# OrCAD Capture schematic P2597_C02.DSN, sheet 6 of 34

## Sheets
6 28_5V & 3V3 Vregs: size Custom
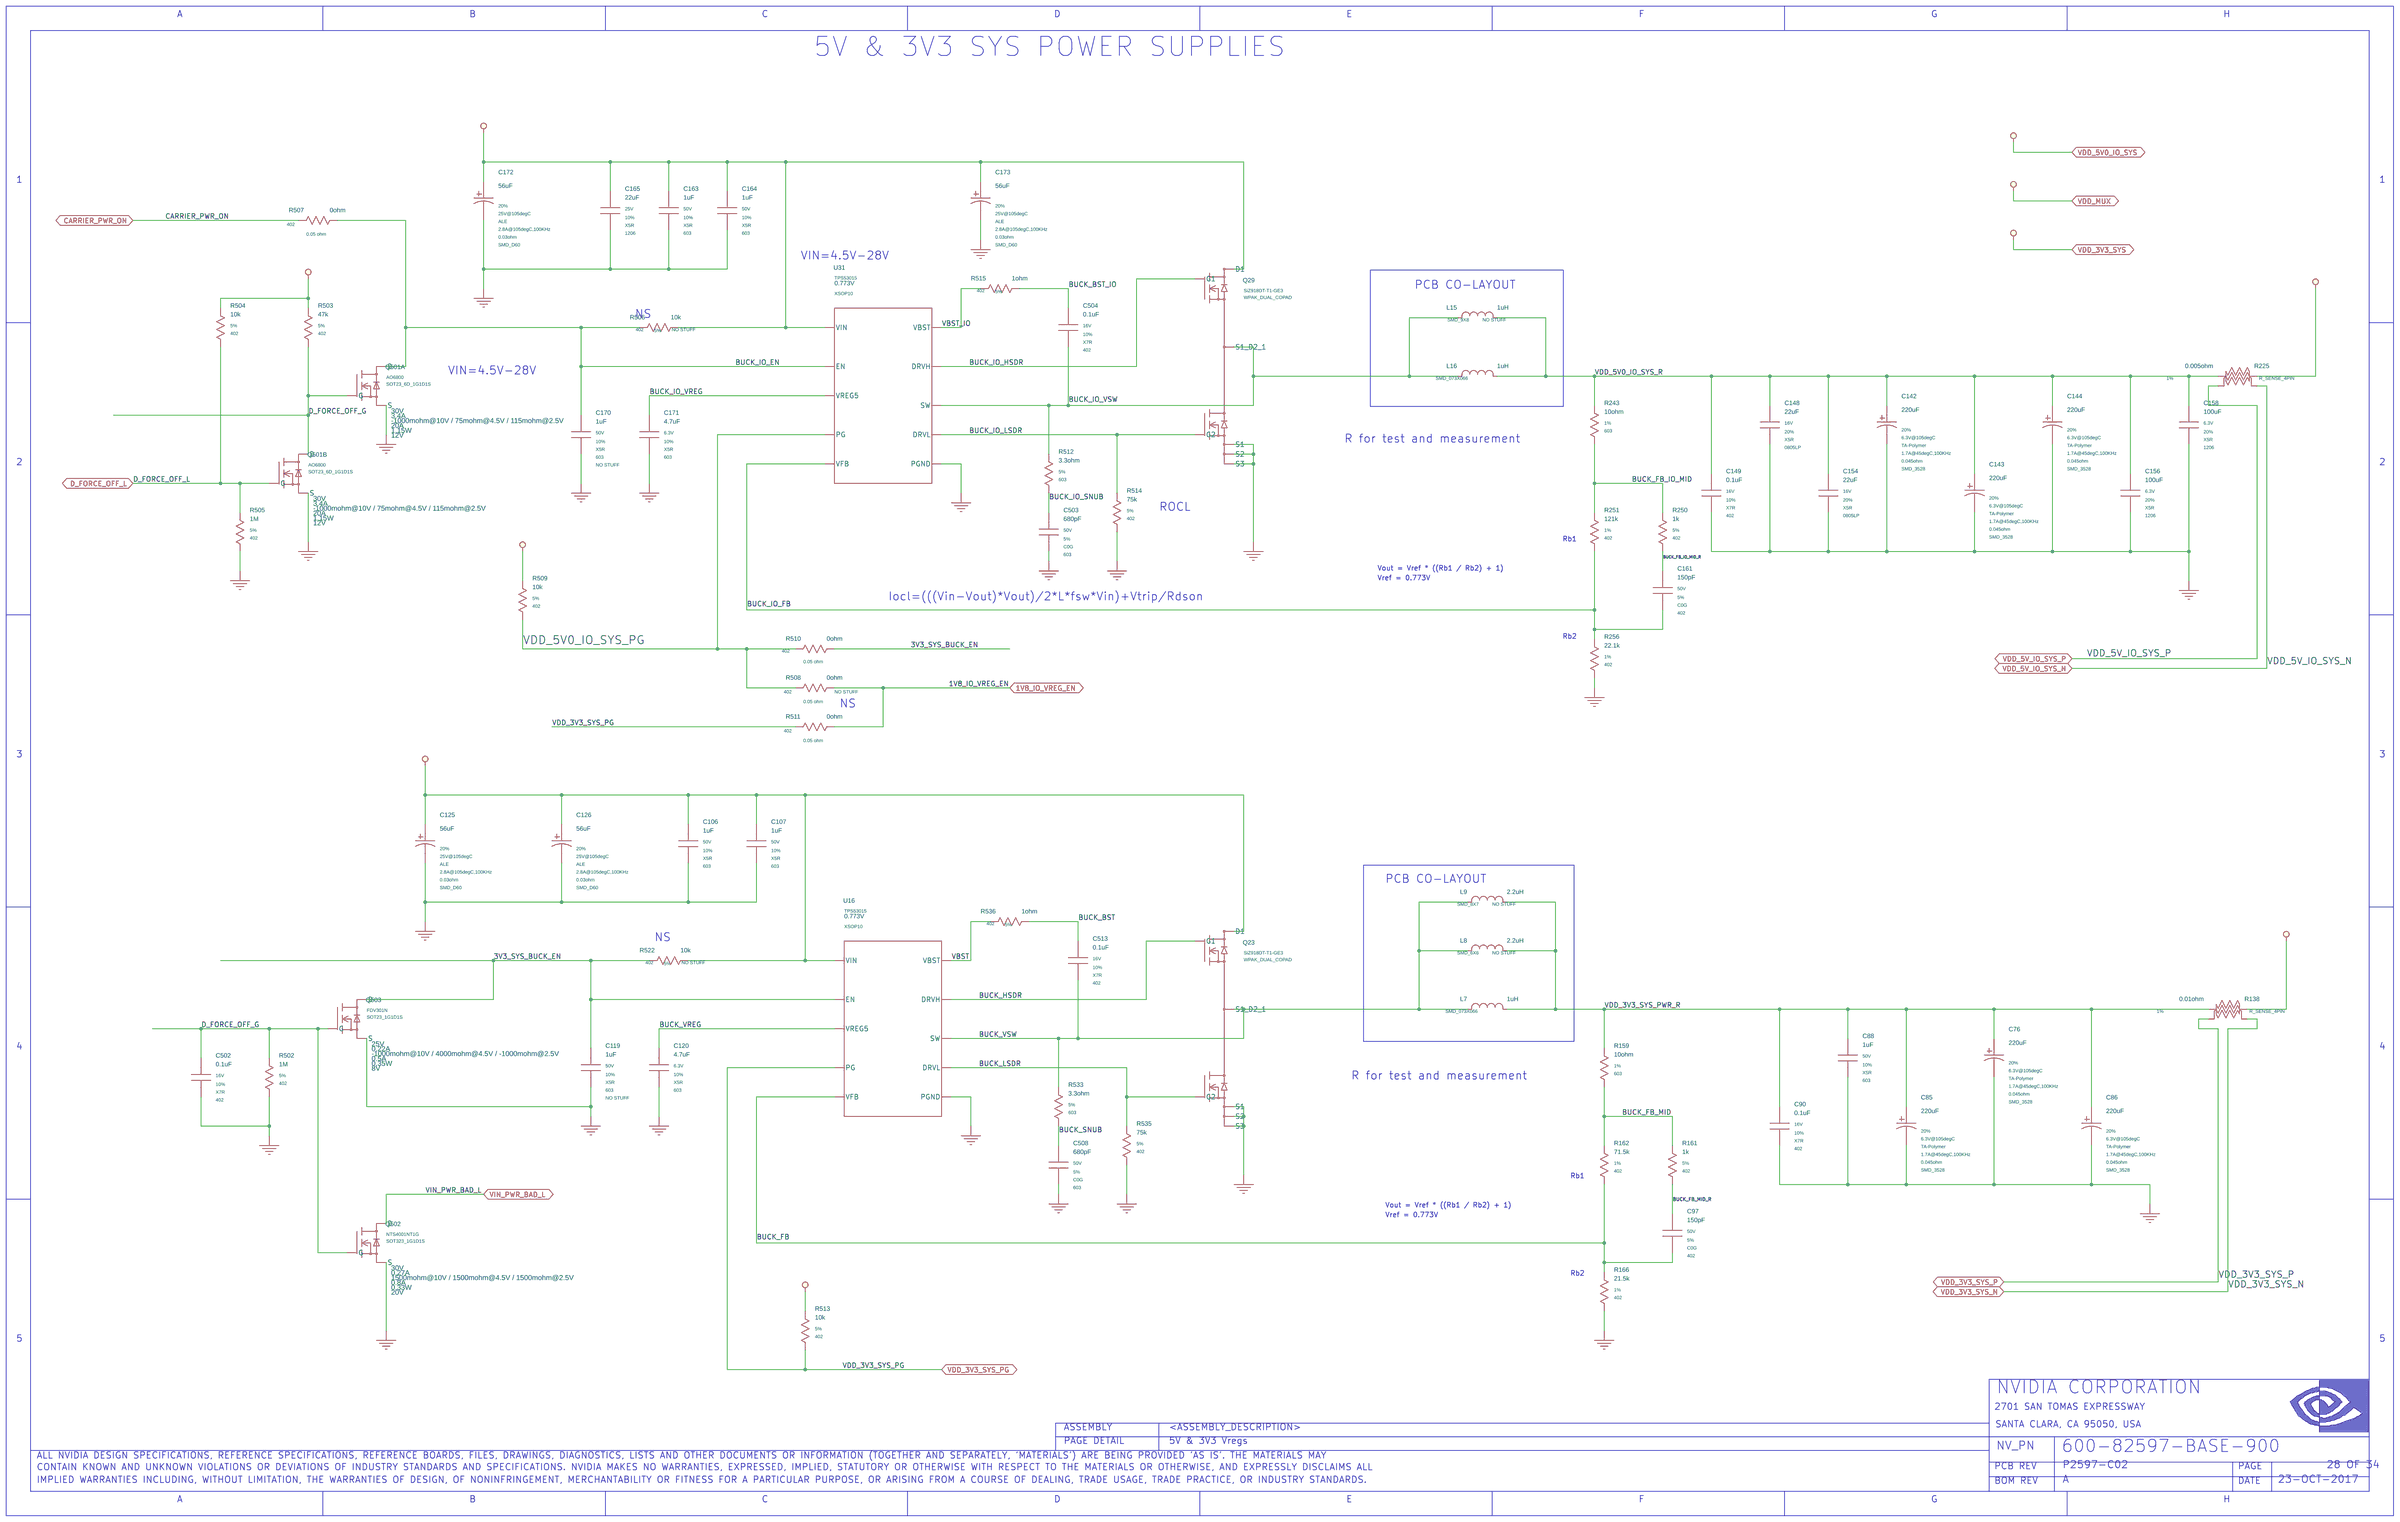
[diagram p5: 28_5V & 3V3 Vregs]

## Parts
C76  220uF  [CAP_SMD_3528]
C85  220uF  [CAP_SMD_3528]
C86  220uF  [CAP_SMD_3528]
C88  1uF  [603]
C90  0.1uF  [402]
C97  150pF  [402]
C106  1uF  [603]
C107  1uF  [603]
C119  1uF  [603]
C120  4.7uF  [603]
C125  56uF  [CAP_SMD_066X066]
C126  56uF  [CAP_SMD_066X066]
C142  220uF  [CAP_SMD_3528]
C143  220uF  [CAP_SMD_3528]
C144  220uF  [CAP_SMD_3528]
C148  22uF  [805]
C149  0.1uF  [402]
C154  22uF  [805]
C156  100uF  [1206]
C158  100uF  [1206]
C161  150pF  [402]
C163  1uF  [603]
C164  1uF  [603]
C165  22uF  [1206]
C170  1uF  [603]
C171  4.7uF  [603]
C172  56uF  [CAP_SMD_066X066]
C173  56uF  [CAP_SMD_066X066]
C502  0.1uF  [402]
C503  680pF  [603]
C504  0.1uF  [402]
C508  680pF  [603]
C513  0.1uF  [402]
L7  1uH  [IND_NONRKO_SMD_073X066]
L8  2.2uH  [IND_NONRKO_SMD_065X069]
L9  2.2uH  [IND_NONRKO_SMD_078X072]
L15  1uH  [IND_NONRKO_SMD_088X084]
L16  1uH  [IND_NONRKO_SMD_073X066]
Q23  Q_FET_N_ENH  [DFET_SMD_056X052_VIAS]
Q29  Q_FET_N_ENH  [DFET_SMD_056X052_VIAS]
Q501  Q_FET_N_ENH  [SOT23_6]  (sections A,B)
Q502  Q_FET_N_ENH  [SOT323]
Q503  Q_FET_N_ENH  [SOT23]
R138  0.01ohm  [RES_04_SMD_015X032]
R159  10ohm  [603]
R161  1k  [402]
R162  71.5k  [402]
R166  21.5k  [402]
R225  0.005ohm  [RES_04_SMD_015X032]
R243  10ohm  [603]
R250  1k  [402]
R251  121k  [402]
R256  22.1k  [402]
R502  1M  [402]
R503  47k  [402]
R504  10k  [402]
R505  1M  [402]
R506  10k  [402]
R507  0ohm  [402]
R508  0ohm  [402]
R509  10k  [402]
R510  0ohm  [402]
R511  0ohm  [402]
R512  3.3ohm  [603]
R513  10k  [402]
R514  75k  [402]
R515  1ohm  [402]
R522  10k  [402]
R533  3.3ohm  [603]
R535  75k  [402]
R536  1ohm  [402]
U16  0.773V  [XSOP10_P050_030X030]
U31  0.773V  [XSOP10_P050_030X030]

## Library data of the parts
C76 = C_POL: ASSEMBLY: VR_3V3; CDS_LIB: discrete; CDS_PART_NAME: C_POL_SMD_3528-220UF,TA-POLYMER,20%,6.3V@105DEGC,0.045OHM,9.999UH,1.7A@45DEGC,100KHZ,041-0177-000; CDS_PHYS_PART_NAME: C_POL_SMD_3528-220UF,TA-POLYMER,20%,6.3V@105DEGC,0.045OHM,9.999UH,1.7A@45DEGC,100KHZ,041-0177-000-041-0177-000,220UF; CDS_SEC: 1; DEVICE_TYPENAME: C_POL_SMD_3528-220UFTA-POLYMER2063V105DEGC0045OHM9999UH17A45DEGC100KHZ041-0177-000-041-0177-000220UF; DRAWING: @P2597_C02_LIB.P2597_C02(SCH_1):PAGE28; ESL: 9.999uH; ESR: 0.045ohm; MAT: TA-Polymer; MAX_VOLTAGE: 6.3V@105degC; NV_PN: 041-0177-000; PACK_TYPE: SMD_3528; PATH: I267; PHYS_PAGE: 28; RIPPLE_CURRENT: 1.7A@45degC,100KHz; ROT: 0; SEC: 1; SIGNAL_MODEL: nv_capp; TOL: 20%; VER: 1; XY: (-1650,-150)
C85 = C_POL: ASSEMBLY: VR_3V3; CDS_LIB: discrete; CDS_PART_NAME: C_POL_SMD_3528-220UF,TA-POLYMER,20%,6.3V@105DEGC,0.045OHM,9.999UH,1.7A@45DEGC,100KHZ,041-0177-000; CDS_PHYS_PART_NAME: C_POL_SMD_3528-220UF,TA-POLYMER,20%,6.3V@105DEGC,0.045OHM,9.999UH,1.7A@45DEGC,100KHZ,041-0177-000-041-0177-000,220UF; CDS_SEC: 1; DEVICE_TYPENAME: C_POL_SMD_3528-220UFTA-POLYMER2063V105DEGC0045OHM9999UH17A45DEGC100KHZ041-0177-000-041-0177-000220UF; DRAWING: @P2597_C02_LIB.P2597_C02(SCH_1):PAGE28; ESL: 9.999uH; ESR: 0.045ohm; MAT: TA-Polymer; MAX_VOLTAGE: 6.3V@105degC; NV_PN: 041-0177-000; PACK_TYPE: SMD_3528; PATH: I266; PHYS_PAGE: 28; RIPPLE_CURRENT: 1.7A@45degC,100KHz; ROT: 0; SEC: 1; SIGNAL_MODEL: nv_capp; TOL: 20%; VER: 1; XY: (-2100,-500)
C86 = C_POL: ASSEMBLY: VR_3V3; CDS_LIB: discrete; CDS_PART_NAME: C_POL_SMD_3528-220UF,TA-POLYMER,20%,6.3V@105DEGC,0.045OHM,9.999UH,1.7A@45DEGC,100KHZ,041-0177-000; CDS_PHYS_PART_NAME: C_POL_SMD_3528-220UF,TA-POLYMER,20%,6.3V@105DEGC,0.045OHM,9.999UH,1.7A@45DEGC,100KHZ,041-0177-000-041-0177-000,220UF; CDS_SEC: 1; DEVICE_TYPENAME: C_POL_SMD_3528-220UFTA-POLYMER2063V105DEGC0045OHM9999UH17A45DEGC100KHZ041-0177-000-041-0177-000220UF; DRAWING: @P2597_C02_LIB.P2597_C02(SCH_1):PAGE28; ESL: 9.999uH; ESR: 0.045ohm; MAT: TA-Polymer; MAX_VOLTAGE: 6.3V@105degC; NV_PN: 041-0177-000; PACK_TYPE: SMD_3528; PATH: I268; PHYS_PAGE: 28; RIPPLE_CURRENT: 1.7A@45degC,100KHz; ROT: 0; SEC: 1; SIGNAL_MODEL: nv_capp; TOL: 20%; VER: 1; XY: (-1150,-500)
C88 = C: ASSEMBLY: VR_3V3; CDS_LIB: discrete; CDS_PART_NAME: C_0603-1UF,X5R,10%,50V,039-0222-000; CDS_PHYS_PART_NAME: C_0603-1UF,X5R,10%,50V,039-0222-000-039-0222-000,1UF; CDS_SEC: 1; DEVICE_TYPENAME: C_0603-1UFX5R1050V039-0222-000-039-0222-0001UF; DRAWING: @P2597_C02_LIB.P2597_C02(SCH_1):PAGE28; MAT: X5R; MAX_VOLTAGE: 50V; NV_PN: 039-0222-000; PATH: I265; PHYS_PAGE: 28; ROT: 0; SEC: 1; SIGNAL_MODEL: DEFAULT_CAPACITOR_1e+06pF_2_1; TOL: 10%; VER: 1; XY: (-2400,-150)
C90 = C: ASSEMBLY: VR_3V3; CDS_LIB: discrete; CDS_PART_NAME: C_0402-0.1UF,X7R,10%,16V,036-0014-000; CDS_PHYS_PART_NAME: C_0402-0.1UF,X7R,10%,16V,036-0014-000-0.1UF,036-0014-000; CDS_SEC: 1; DEVICE_TYPENAME: C_0402-01UFX7R1016V036-0014-000-01UF036-0014-000; DRAWING: @P2597_C02_LIB.P2597_C02(SCH_1):PAGE28; MAT: X7R; MAX_VOLTAGE: 16V; NV_PN: 036-0014-000; PATH: I264; PHYS_PAGE: 28; ROT: 0; SEC: 1; SIGNAL_MODEL: DEFAULT_CAPACITOR_100000pF_2_1; TOL: 10%; VER: 1; XY: (-2750,-500)
C97 = C: ASSEMBLY: VR_3V3; CDS_LIB: discrete; CDS_PART_NAME: C_0402-150PF,C0G,5%,50V,035-0018-000; CDS_PHYS_PART_NAME: C_0402-150PF,C0G,5%,50V,035-0018-000-035-0018-000,150PF; CDS_SEC: 1; DEVICE_TYPENAME: C_0402-150PFC0G550V035-0018-000-035-0018-000150PF; DRAWING: @P2597_C02_LIB.P2597_C02(SCH_1):PAGE28; MAT: C0G; MAX_VOLTAGE: 50V; NV_PN: 035-0018-000; PATH: I135; PHYS_PAGE: 28; ROT: 0; SEC: 1; SIGNAL_MODEL: nv_cap; TOL: 5%; VER: 1; XY: (-3300,-1050)
C106 = C: ASSEMBLY: VR_3V3; CDS_LIB: discrete; CDS_PART_NAME: C_0603-1UF,X5R,10%,50V,039-0222-000; CDS_PHYS_PART_NAME: C_0603-1UF,X5R,10%,50V,039-0222-000-039-0222-000,1UF; CDS_SEC: 1; DEVICE_TYPENAME: C_0603-1UFX5R1050V039-0222-000-039-0222-0001UF; DRAWING: @P2597_C02_LIB.P2597_C02(SCH_1):PAGE28; MAT: X5R; MAX_VOLTAGE: 50V; NV_PN: 039-0222-000; PATH: I149; PHYS_PAGE: 28; ROT: 0; SEC: 1; SIGNAL_MODEL: DEFAULT_CAPACITOR_1e+06pF_2_1; TOL: 10%; VER: 1; XY: (-8350,950)
C107 = C: ASSEMBLY: VR_5V; CDS_LIB: discrete; CDS_PART_NAME: C_0603-1UF,X5R,10%,50V,039-0222-000; CDS_PHYS_PART_NAME: C_0603-1UF,X5R,10%,50V,039-0222-000-039-0222-000,1UF; CDS_SEC: 1; DEVICE_TYPENAME: C_0603-1UFX5R1050V039-0222-000-039-0222-0001UF; DRAWING: @P2597_C02_LIB.P2597_C02(SCH_1):PAGE28; MAT: X5R; MAX_VOLTAGE: 50V; NV_PN: 039-0222-000; PATH: I233; PHYS_PAGE: 28; ROT: 0; SEC: 1; SIGNAL_MODEL: DEFAULT_CAPACITOR_1e+06pF_2_1; TOL: 10%; VER: 1; XY: (-8000,950)
C119 = C: ASSEMBLY: VR_3V3; CDS_LIB: discrete; CDS_PART_NAME: C_0603-1UF,X5R,10%,50V,039-0222-000; CDS_PHYS_PART_NAME: C_0603-1UF,X5R,10%,50V,039-0222-000-039-0222-000,1UF; CDS_SEC: 1; DEVICE_TYPENAME: C_0603-1UFX5R1050V039-0222-000-039-0222-0001UF; DRAWING: @P2597_C02_LIB.P2597_C02(SCH_1):PAGE28; MAT: X5R; MAX_VOLTAGE: 50V; NV_PN: 039-0222-000; PATH: I162; PHYS_PAGE: 28; ROT: 0; SEC: 1; SIGNAL_MODEL: DEFAULT_CAPACITOR_1e+06pF_2_1; SKU: NO STUFF; TOL: 10%; VER: 1; XY: (-8850,-200)
C120 = C: ASSEMBLY: VR_3V3; CDS_LIB: discrete; CDS_PART_NAME: C_0603-4.7UF,X5R,10%,6.3V,039-0037-000; CDS_PHYS_PART_NAME: C_0603-4.7UF,X5R,10%,6.3V,039-0037-000-039-0037-000,4.7UF; CDS_SEC: 1; DEVICE_TYPENAME: C_0603-47UFX5R1063V039-0037-000-039-0037-00047UF; DRAWING: @P2597_C02_LIB.P2597_C02(SCH_1):PAGE28; ESL: N/A; ESR: N/A; MAT: X5R; MAX_VOLTAGE: 6.3V; NV_PN: 039-0037-000; PATH: I152; PHYS_PAGE: 28; ROT: 0; SEC: 1; SIGNAL_MODEL: nv_cap; TOL: 10%; VER: 1; XY: (-8500,-200)
C125 = C_POL: ASSEMBLY: VR_3V3; CDS_LIB: discrete; CDS_PART_NAME: C_POL_SMD_D60-56UF,ALE,20%,25V@105DEGC,0.03OHM,9.999UH,2.8A@105DEGC,100KHZ,032-0240-000; CDS_PHYS_PART_NAME: C_POL_SMD_D60-56UF,ALE,20%,25V@105DEGC,0.03OHM,9.999UH,2.8A@105DEGC,100KHZ,032-0240-000-032-0240-000,56UF; CDS_SEC: 1; DEVICE_TYPENAME: C_POL_SMD_D60-56UFALE2025V105DEGC003OHM9999UH28A105DEGC100KHZ032-0240-000-032-0240-00056UF; DRAWING: @P2597_C02_LIB.P2597_C02(SCH_1):PAGE28; ESL: 9.999uH; ESR: 0.03ohm; MAT: ALE; MAX_VOLTAGE: 25V@105degC; NV_PN: 032-0240-000; PACK_TYPE: SMD_D60; PATH: I259; PHYS_PAGE: 28; RIPPLE_CURRENT: 2.8A@105degC,100KHz; ROT: 0; SEC: 1; SIGNAL_MODEL: nv_capp; TOL: 20%; VER: 1; XY: (-9700,950)
C126 = C_POL: ASSEMBLY: VR_3V3; CDS_LIB: discrete; CDS_PART_NAME: C_POL_SMD_D60-56UF,ALE,20%,25V@105DEGC,0.03OHM,9.999UH,2.8A@105DEGC,100KHZ,032-0240-000; CDS_PHYS_PART_NAME: C_POL_SMD_D60-56UF,ALE,20%,25V@105DEGC,0.03OHM,9.999UH,2.8A@105DEGC,100KHZ,032-0240-000-032-0240-000,56UF; CDS_SEC: 1; DEVICE_TYPENAME: C_POL_SMD_D60-56UFALE2025V105DEGC003OHM9999UH28A105DEGC100KHZ032-0240-000-032-0240-00056UF; DRAWING: @P2597_C02_LIB.P2597_C02(SCH_1):PAGE28; ESL: 9.999uH; ESR: 0.03ohm; MAT: ALE; MAX_VOLTAGE: 25V@105degC; NV_PN: 032-0240-000; PACK_TYPE: SMD_D60; PATH: I258; PHYS_PAGE: 28; RIPPLE_CURRENT: 2.8A@105degC,100KHz; ROT: 0; SEC: 1; SIGNAL_MODEL: nv_capp; TOL: 20%; VER: 1; XY: (-9000,950)
C142 = C_POL: ASSEMBLY: VR_5V; CDS_LIB: discrete; CDS_PART_NAME: C_POL_SMD_3528-220UF,TA-POLYMER,20%,6.3V@105DEGC,0.045OHM,9.999UH,1.7A@45DEGC,100KHZ,041-0177-000; CDS_PHYS_PART_NAME: C_POL_SMD_3528-220UF,TA-POLYMER,20%,6.3V@105DEGC,0.045OHM,9.999UH,1.7A@45DEGC,100KHZ,041-0177-000-041-0177-000,220UF; CDS_SEC: 1; DEVICE_TYPENAME: C_POL_SMD_3528-220UFTA-POLYMER2063V105DEGC0045OHM9999UH17A45DEGC100KHZ041-0177-000-041-0177-000220UF; DRAWING: @P2597_C02_LIB.P2597_C02(SCH_1):PAGE28; ESL: 9.999uH; ESR: 0.045ohm; MAT: TA-Polymer; MAX_VOLTAGE: 6.3V@105degC; NV_PN: 041-0177-000; PACK_TYPE: SMD_3528; PATH: I261; PHYS_PAGE: 28; RIPPLE_CURRENT: 1.7A@45degC,100KHz; ROT: 0; SEC: 1; SIGNAL_MODEL: nv_capp; TOL: 20%; VER: 1; XY: (-2200,3100)
C143 = C_POL: ASSEMBLY: VR_5V; CDS_LIB: discrete; CDS_PART_NAME: C_POL_SMD_3528-220UF,TA-POLYMER,20%,6.3V@105DEGC,0.045OHM,9.999UH,1.7A@45DEGC,100KHZ,041-0177-000; CDS_PHYS_PART_NAME: C_POL_SMD_3528-220UF,TA-POLYMER,20%,6.3V@105DEGC,0.045OHM,9.999UH,1.7A@45DEGC,100KHZ,041-0177-000-041-0177-000,220UF; CDS_SEC: 1; DEVICE_TYPENAME: C_POL_SMD_3528-220UFTA-POLYMER2063V105DEGC0045OHM9999UH17A45DEGC100KHZ041-0177-000-041-0177-000220UF; DRAWING: @P2597_C02_LIB.P2597_C02(SCH_1):PAGE28; ESL: 9.999uH; ESR: 0.045ohm; MAT: TA-Polymer; MAX_VOLTAGE: 6.3V@105degC; NV_PN: 041-0177-000; PACK_TYPE: SMD_3528; PATH: I262; PHYS_PAGE: 28; RIPPLE_CURRENT: 1.7A@45degC,100KHz; ROT: 0; SEC: 1; SIGNAL_MODEL: nv_capp; TOL: 20%; VER: 1; XY: (-1750,2750)
C144 = C_POL: ASSEMBLY: VR_5V; CDS_LIB: discrete; CDS_PART_NAME: C_POL_SMD_3528-220UF,TA-POLYMER,20%,6.3V@105DEGC,0.045OHM,9.999UH,1.7A@45DEGC,100KHZ,041-0177-000; CDS_PHYS_PART_NAME: C_POL_SMD_3528-220UF,TA-POLYMER,20%,6.3V@105DEGC,0.045OHM,9.999UH,1.7A@45DEGC,100KHZ,041-0177-000-041-0177-000,220UF; CDS_SEC: 1; DEVICE_TYPENAME: C_POL_SMD_3528-220UFTA-POLYMER2063V105DEGC0045OHM9999UH17A45DEGC100KHZ041-0177-000-041-0177-000220UF; DRAWING: @P2597_C02_LIB.P2597_C02(SCH_1):PAGE28; ESL: 9.999uH; ESR: 0.045ohm; MAT: TA-Polymer; MAX_VOLTAGE: 6.3V@105degC; NV_PN: 041-0177-000; PACK_TYPE: SMD_3528; PATH: I263; PHYS_PAGE: 28; RIPPLE_CURRENT: 1.7A@45degC,100KHz; ROT: 0; SEC: 1; SIGNAL_MODEL: nv_capp; TOL: 20%; VER: 1; XY: (-1350,3100)
C148 = C: ASSEMBLY: VR_5V; CDS_LIB: discrete; CDS_PART_NAME: C_0805LP-22UF,X5R,20%,16V,032-0195-000; CDS_PHYS_PART_NAME: C_0805LP-22UF,X5R,20%,16V,032-0195-000-032-0195-000,22UF; CDS_SEC: 1; DEVICE_TYPENAME: C_0805LP-22UFX5R2016V032-0195-000-032-0195-00022UF; DRAWING: @P2597_C02_LIB.P2597_C02(SCH_1):PAGE28; MAT: X5R; MAX_VOLTAGE: 16V; NV_PN: 032-0195-000; PACK_TYPE: 0805LP; PATH: I41; PHYS_PAGE: 28; ROT: 0; SEC: 1; SEC_TYPE: 0805LP; SIGNAL_MODEL: nv_cap; TOL: 20%; VER: 1; XY: (-2800,3100)
C149 = C: ASSEMBLY: VR_5V; CDS_LIB: discrete; CDS_PART_NAME: C_0402-0.1UF,X7R,10%,16V,036-0014-000; CDS_PHYS_PART_NAME: C_0402-0.1UF,X7R,10%,16V,036-0014-000-0.1UF,036-0014-000; CDS_SEC: 1; DEVICE_TYPENAME: C_0402-01UFX7R1016V036-0014-000-01UF036-0014-000; DRAWING: @P2597_C02_LIB.P2597_C02(SCH_1):PAGE28; MAT: X7R; MAX_VOLTAGE: 16V; NV_PN: 036-0014-000; PATH: I50; PHYS_PAGE: 28; ROT: 0; SEC: 1; SIGNAL_MODEL: DEFAULT_CAPACITOR_100000pF_2_1; TOL: 10%; VER: 1; XY: (-3100,2750)
C154 = C: ASSEMBLY: VR_5V; CDS_LIB: discrete; CDS_PART_NAME: C_0805LP-22UF,X5R,20%,16V,032-0195-000; CDS_PHYS_PART_NAME: C_0805LP-22UF,X5R,20%,16V,032-0195-000-032-0195-000,22UF; CDS_SEC: 1; DEVICE_TYPENAME: C_0805LP-22UFX5R2016V032-0195-000-032-0195-00022UF; DRAWING: @P2597_C02_LIB.P2597_C02(SCH_1):PAGE28; MAT: X5R; MAX_VOLTAGE: 16V; NV_PN: 032-0195-000; PACK_TYPE: 0805LP; PATH: I45; PHYS_PAGE: 28; ROT: 0; SEC: 1; SEC_TYPE: 0805LP; SIGNAL_MODEL: nv_cap; TOL: 20%; VER: 1; XY: (-2500,2750)
C156 = C: ASSEMBLY: VR_5V; CDS_LIB: discrete; CDS_PART_NAME: C_1206-100UF,X5R,20%,6.3V,039-0148-000; CDS_PHYS_PART_NAME: C_1206-100UF,X5R,20%,6.3V,039-0148-000-039-0148-000,100UF; CDS_SEC: 1; DEVICE_TYPENAME: C_1206-100UFX5R2063V039-0148-000-039-0148-000100UF; DRAWING: @P2597_C02_LIB.P2597_C02(SCH_1):PAGE28; MAT: X5R; MAX_VOLTAGE: 6.3V; NV_PN: 039-0148-000; PATH: I234; PHYS_PAGE: 28; ROT: 0; SEC: 1; SIGNAL_MODEL: DEFAULT_CAPACITOR_1e+08pF_2_1; TOL: 20%; VER: 1; XY: (-950,2750)
C158 = C: ASSEMBLY: VR_5V; CDS_LIB: discrete; CDS_PART_NAME: C_1206-100UF,X5R,20%,6.3V,039-0148-000; CDS_PHYS_PART_NAME: C_1206-100UF,X5R,20%,6.3V,039-0148-000-039-0148-000,100UF; CDS_SEC: 1; DEVICE_TYPENAME: C_1206-100UFX5R2063V039-0148-000-039-0148-000100UF; DRAWING: @P2597_C02_LIB.P2597_C02(SCH_1):PAGE28; MAT: X5R; MAX_VOLTAGE: 6.3V; NV_PN: 039-0148-000; PATH: I235; PHYS_PAGE: 28; ROT: 0; SEC: 1; SIGNAL_MODEL: DEFAULT_CAPACITOR_1e+08pF_2_1; TOL: 20%; VER: 1; XY: (-650,3100)
C161 = C: ASSEMBLY: VR_5V; CDS_LIB: discrete; CDS_PART_NAME: C_0402-150PF,C0G,5%,50V,035-0018-000; CDS_PHYS_PART_NAME: C_0402-150PF,C0G,5%,50V,035-0018-000-035-0018-000,150PF; CDS_SEC: 1; DEVICE_TYPENAME: C_0402-150PFC0G550V035-0018-000-035-0018-000150PF; DRAWING: @P2597_C02_LIB.P2597_C02(SCH_1):PAGE28; MAT: C0G; MAX_VOLTAGE: 50V; NV_PN: 035-0018-000; PATH: I40; PHYS_PAGE: 28; ROT: 0; SEC: 1; SIGNAL_MODEL: nv_cap; TOL: 5%; VER: 1; XY: (-3350,2250)
C163 = C: ASSEMBLY: VR_5V; CDS_LIB: discrete; CDS_PART_NAME: C_0603-1UF,X5R,10%,50V,039-0222-000; CDS_PHYS_PART_NAME: C_0603-1UF,X5R,10%,50V,039-0222-000-039-0222-000,1UF; CDS_SEC: 1; DEVICE_TYPENAME: C_0603-1UFX5R1050V039-0222-000-039-0222-0001UF; DRAWING: @P2597_C02_LIB.P2597_C02(SCH_1):PAGE28; MAT: X5R; MAX_VOLTAGE: 50V; NV_PN: 039-0222-000; PATH: I11; PHYS_PAGE: 28; ROT: 0; SEC: 1; SIGNAL_MODEL: DEFAULT_CAPACITOR_1e+06pF_2_1; TOL: 10%; VER: 1; XY: (-8450,4200)
C164 = C: ASSEMBLY: VR_5V; CDS_LIB: discrete; CDS_PART_NAME: C_0603-1UF,X5R,10%,50V,039-0222-000; CDS_PHYS_PART_NAME: C_0603-1UF,X5R,10%,50V,039-0222-000-039-0222-000,1UF; CDS_SEC: 1; DEVICE_TYPENAME: C_0603-1UFX5R1050V039-0222-000-039-0222-0001UF; DRAWING: @P2597_C02_LIB.P2597_C02(SCH_1):PAGE28; MAT: X5R; MAX_VOLTAGE: 50V; NV_PN: 039-0222-000; PATH: I232; PHYS_PAGE: 28; ROT: 0; SEC: 1; SIGNAL_MODEL: DEFAULT_CAPACITOR_1e+06pF_2_1; TOL: 10%; VER: 1; XY: (-8150,4200)
C165 = C: ASSEMBLY: VR_5V; CDS_LIB: discrete; CDS_PART_NAME: C_1206-22UF,X5R,10%,25V,039-0213-000; CDS_PHYS_PART_NAME: C_1206-22UF,X5R,10%,25V,039-0213-000-039-0213-000,22UF; CDS_SEC: 1; DEVICE_TYPENAME: C_1206-22UFX5R1025V039-0213-000-039-0213-00022UF; DRAWING: @P2597_C02_LIB.P2597_C02(SCH_1):PAGE28; MAT: X5R; MAX_VOLTAGE: 25V; NV_PN: 039-0213-000; PATH: I4; PHYS_PAGE: 28; ROT: 0; SEC: 1; SIGNAL_MODEL: DEFAULT_CAPACITOR_2.2e+07pF_2_1; TOL: 10%; VER: 1; XY: (-8750,4200)
C170 = C: ASSEMBLY: VR_5V; CDS_LIB: discrete; CDS_PART_NAME: C_0603-1UF,X5R,10%,50V,039-0222-000; CDS_PHYS_PART_NAME: C_0603-1UF,X5R,10%,50V,039-0222-000-039-0222-000,1UF; CDS_SEC: 1; DEVICE_TYPENAME: C_0603-1UFX5R1050V039-0222-000-039-0222-0001UF; DRAWING: @P2597_C02_LIB.P2597_C02(SCH_1):PAGE28; MAT: X5R; MAX_VOLTAGE: 50V; NV_PN: 039-0222-000; PATH: I2; PHYS_PAGE: 28; ROT: 0; SEC: 1; SIGNAL_MODEL: DEFAULT_CAPACITOR_1e+06pF_2_1; SKU: NO STUFF; TOL: 10%; VER: 1; XY: (-8900,3050)
C171 = C: ASSEMBLY: VR_5V; CDS_LIB: discrete; CDS_PART_NAME: C_0603-4.7UF,X5R,10%,6.3V,039-0037-000; CDS_PHYS_PART_NAME: C_0603-4.7UF,X5R,10%,6.3V,039-0037-000-039-0037-000,4.7UF; CDS_SEC: 1; DEVICE_TYPENAME: C_0603-47UFX5R1063V039-0037-000-039-0037-00047UF; DRAWING: @P2597_C02_LIB.P2597_C02(SCH_1):PAGE28; ESL: N/A; ESR: N/A; MAT: X5R; MAX_VOLTAGE: 6.3V; NV_PN: 039-0037-000; PATH: I8; PHYS_PAGE: 28; ROT: 0; SEC: 1; SIGNAL_MODEL: nv_cap; TOL: 10%; VER: 1; XY: (-8550,3050)
C172 = C_POL: ASSEMBLY: VR_5V; CDS_LIB: discrete; CDS_PART_NAME: C_POL_SMD_D60-56UF,ALE,20%,25V@105DEGC,0.03OHM,9.999UH,2.8A@105DEGC,100KHZ,032-0240-000; CDS_PHYS_PART_NAME: C_POL_SMD_D60-56UF,ALE,20%,25V@105DEGC,0.03OHM,9.999UH,2.8A@105DEGC,100KHZ,032-0240-000-032-0240-000,56UF; CDS_SEC: 1; DEVICE_TYPENAME: C_POL_SMD_D60-56UFALE2025V105DEGC003OHM9999UH28A105DEGC100KHZ032-0240-000-032-0240-00056UF; DRAWING: @P2597_C02_LIB.P2597_C02(SCH_1):PAGE28; ESL: 9.999uH; ESR: 0.03ohm; MAT: ALE; MAX_VOLTAGE: 25V@105degC; NV_PN: 032-0240-000; PACK_TYPE: SMD_D60; PATH: I260; PHYS_PAGE: 28; RIPPLE_CURRENT: 2.8A@105degC,100KHz; ROT: 0; SEC: 1; SIGNAL_MODEL: nv_capp; TOL: 20%; VER: 1; XY: (-9400,4250)
C173 = C_POL: ASSEMBLY: VR_5V; CDS_LIB: discrete; CDS_PART_NAME: C_POL_SMD_D60-56UF,ALE,20%,25V@105DEGC,0.03OHM,9.999UH,2.8A@105DEGC,100KHZ,032-0240-000; CDS_PHYS_PART_NAME: C_POL_SMD_D60-56UF,ALE,20%,25V@105DEGC,0.03OHM,9.999UH,2.8A@105DEGC,100KHZ,032-0240-000-032-0240-000,56UF; CDS_SEC: 1; DEVICE_TYPENAME: C_POL_SMD_D60-56UFALE2025V105DEGC003OHM9999UH28A105DEGC100KHZ032-0240-000-032-0240-00056UF; DRAWING: @P2597_C02_LIB.P2597_C02(SCH_1):PAGE28; ESL: 9.999uH; ESR: 0.03ohm; MAT: ALE; MAX_VOLTAGE: 25V@105degC; NV_PN: 032-0240-000; PACK_TYPE: SMD_D60; PATH: I256; PHYS_PAGE: 28; RIPPLE_CURRENT: 2.8A@105degC,100KHz; ROT: 0; SEC: 1; SIGNAL_MODEL: nv_capp; TOL: 20%; VER: 1; XY: (-6850,4250)
C502 = C: ASSEMBLY: VR_5V; CDS_LIB: discrete; CDS_PART_NAME: C_0402-0.1UF,X7R,10%,16V,036-0014-000; CDS_PHYS_PART_NAME: C_0402-0.1UF,X7R,10%,16V,036-0014-000-0.1UF,036-0014-000; CDS_SEC: 1; DEVICE_TYPENAME: C_0402-01UFX7R1016V036-0014-000-01UF036-0014-000; DRAWING: @P2597_C02_LIB.P2597_C02(SCH_1):PAGE28; MAT: X7R; MAX_VOLTAGE: 16V; NV_PN: 036-0014-000; PATH: I270; PHYS_PAGE: 28; ROT: 0; SEC: 1; SIGNAL_MODEL: DEFAULT_CAPACITOR_100000pF_2_1; TOL: 10%; VER: 1; XY: (-10850,-250)
C503 = C: ASSEMBLY: VR_5V; CDS_LIB: discrete; CDS_PART_NAME: C_0603-680PF,C0G,5%,50V,035-0060-000; CDS_PHYS_PART_NAME: C_0603-680PF,C0G,5%,50V,035-0060-000-035-0060-000,680PF; CDS_SEC: 1; DEVICE_TYPENAME: C_0603-680PFC0G550V035-0060-000-035-0060-000680PF; DRAWING: @P2597_C02_LIB.P2597_C02(SCH_1):PAGE28; MAT: C0G; MAX_VOLTAGE: 50V; NV_PN: 035-0060-000; PATH: I23; PHYS_PAGE: 28; ROT: 0; SEC: 1; SIGNAL_MODEL: nv_cap; TOL: 5%; VER: 1; XY: (-6500,2550)
C504 = C: ASSEMBLY: VR_5V; CDS_LIB: discrete; CDS_PART_NAME: C_0402-0.1UF,X7R,10%,16V,036-0014-000; CDS_PHYS_PART_NAME: C_0402-0.1UF,X7R,10%,16V,036-0014-000-0.1UF,036-0014-000; CDS_SEC: 1; DEVICE_TYPENAME: C_0402-01UFX7R1016V036-0014-000-01UF036-0014-000; DRAWING: @P2597_C02_LIB.P2597_C02(SCH_1):PAGE28; MAT: X7R; MAX_VOLTAGE: 16V; NV_PN: 036-0014-000; PATH: I29; PHYS_PAGE: 28; ROT: 0; SEC: 1; SIGNAL_MODEL: DEFAULT_CAPACITOR_100000pF_2_1; TOL: 10%; VER: 1; XY: (-6400,3600)
C508 = C: ASSEMBLY: VR_3V3; CDS_LIB: discrete; CDS_PART_NAME: C_0603-680PF,C0G,5%,50V,035-0060-000; CDS_PHYS_PART_NAME: C_0603-680PF,C0G,5%,50V,035-0060-000-035-0060-000,680PF; CDS_SEC: 1; DEVICE_TYPENAME: C_0603-680PFC0G550V035-0060-000-035-0060-000680PF; DRAWING: @P2597_C02_LIB.P2597_C02(SCH_1):PAGE28; MAT: C0G; MAX_VOLTAGE: 50V; NV_PN: 035-0060-000; PATH: I147; PHYS_PAGE: 28; ROT: 0; SEC: 1; SIGNAL_MODEL: nv_cap; TOL: 5%; VER: 1; XY: (-6450,-700)
C513 = C: ASSEMBLY: VR_3V3; CDS_LIB: discrete; CDS_PART_NAME: C_0402-0.1UF,X7R,10%,16V,036-0014-000; CDS_PHYS_PART_NAME: C_0402-0.1UF,X7R,10%,16V,036-0014-000-0.1UF,036-0014-000; CDS_SEC: 1; DEVICE_TYPENAME: C_0402-01UFX7R1016V036-0014-000-01UF036-0014-000; DRAWING: @P2597_C02_LIB.P2597_C02(SCH_1):PAGE28; MAT: X7R; MAX_VOLTAGE: 16V; NV_PN: 036-0014-000; PATH: I141; PHYS_PAGE: 28; ROT: 0; SEC: 1; SIGNAL_MODEL: DEFAULT_CAPACITOR_100000pF_2_1; TOL: 10%; VER: 1; XY: (-6350,350)
L7 = L: ACOUSTIC_MARGIN: [ ]; ASSEMBLY: VR_3V3; CDS_LIB: discrete; CDS_PART_NAME: L_SMD_073X066-1UH,CARBONYL POWDER,20%,11A,22A,0.01OHM,[ ]@[ ],[ ],[ ],130-0776-000; CDS_PHYS_PART_NAME: L_SMD_073X066-1UH,CARBONYL POWDER,20%,11A,22A,0.01OHM,[ ]@[ ],[ ],[ ],130-0776-000-130-0776-000,1UH; CDS_SEC: 1; CONTINUOUS_CURRENT: 11A; DC_RESISTANCE: 0.01ohm; DEVICE_TYPENAME: L_SMD_073X066-1UHCARBONYLPOWDER2011A22A001OHM130-0776-000-130-0776-0001UH; DRAWING: @P2597_C02_LIB.P2597_C02(SCH_1):PAGE28; MAT: Carbonyl Powder; MAX_CURRENT: 22A; NV_PN: 130-0776-000; PACK_TYPE: SMD_073X066; PATH: I133; PHYS_PAGE: 28; PLACEMENT_NOTE: CoLayout with L8, L9; Q: [ ]@[ ]; ROT: 0; SEC: 1; SEC_TYPE: SMD_073X066; SELF_RESONANCE_FREQ: [ ]; SIGNAL_MODEL: nv_ind; TOL: 20%; VER: 1; XY: (-4250,100)
L8 = L: ACOUSTIC_MARGIN: [ ]; ASSEMBLY: VR_3V3; CDS_LIB: discrete; CDS_PART_NAME: L_SMD_6X6-2.2UH,[ ],20%,8A,16A,0.0136OHM,[ ]@[ ],[ ],[ ],131-0352-000; CDS_PHYS_PART_NAME: L_SMD_6X6-2.2UH,[ ],20%,8A,16A,0.0136OHM,[ ]@[ ],[ ],[ ],131-0352-000-131-0352-000,2.2UH; CDS_SEC: 1; CONTINUOUS_CURRENT: 8A; DC_RESISTANCE: 0.0136ohm; DEVICE_TYPENAME: L_SMD_6X6-22UH208A16A00136OHM131-0352-000-131-0352-00022UH; DRAWING: @P2597_C02_LIB.P2597_C02(SCH_1):PAGE28; MAT: [ ]; MAX_CURRENT: 16A; NV_PN: 131-0352-000; PACK_TYPE: SMD_6X6; PATH: I132; PHYS_PAGE: 28; PLACEMENT_NOTE: CoLayout with L7, L9; Q: [ ]@[ ]; ROT: 0; SEC: 1; SEC_TYPE: SMD_6X6; SELF_RESONANCE_FREQ: [ ]; SIGNAL_MODEL: nv_ind; SKU: NO STUFF; TOL: 20%; VER: 1; XY: (-4250,400)
L9 = L: ACOUSTIC_MARGIN: [ ]; ASSEMBLY: VR_3V3; CDS_LIB: discrete; CDS_PART_NAME: L_SMD_8X7-2.2UH,[ ],20%,6A,8A,0.018OHM,[ ]@[ ],[ ],[ ],131-0604-000; CDS_PHYS_PART_NAME: L_SMD_8X7-2.2UH,[ ],20%,6A,8A,0.018OHM,[ ]@[ ],[ ],[ ],131-0604-000-131-0604-000,2.2UH; CDS_SEC: 1; CONTINUOUS_CURRENT: 6A; DC_RESISTANCE: 0.018ohm; DEVICE_TYPENAME: L_SMD_8X7-22UH206A8A0018OHM131-0604-000-131-0604-00022UH; DRAWING: @P2597_C02_LIB.P2597_C02(SCH_1):PAGE28; MAT: [ ]; MAX_CURRENT: 8A; NV_PN: 131-0604-000; PACK_TYPE: SMD_8X7; PATH: I130; PHYS_PAGE: 28; PLACEMENT_NOTE: CoLayout with L7, L8; Q: [ ]@[ ]; ROT: 0; SEC: 1; SEC_TYPE: SMD_8X7; SELF_RESONANCE_FREQ: [ ]; SIGNAL_MODEL: DEFAULT_INDUCTOR_2200nH_2_1; SKU: NO STUFF; TOL: 20%; VER: 1; XY: (-4250,650)
L15 = L: ACOUSTIC_MARGIN: [ ]; ASSEMBLY: VR_5V; CDS_LIB: discrete; CDS_PART_NAME: L_SMD_9X8-1UH,[ ],20%,13A,15A,0.0043OHM,[ ]@[ ],[ ],[ ],131-0653-000; CDS_PHYS_PART_NAME: L_SMD_9X8-1UH,[ ],20%,13A,15A,0.0043OHM,[ ]@[ ],[ ],[ ],131-0653-000-131-0653-000,1UH; CDS_SEC: 1; CONTINUOUS_CURRENT: 13A; DC_RESISTANCE: 0.0043ohm; DEVICE_TYPENAME: L_SMD_9X8-1UH2013A15A00043OHM131-0653-000-131-0653-0001UH; DRAWING: @P2597_C02_LIB.P2597_C02(SCH_1):PAGE28; MAT: [ ]; MAX_CURRENT: 15A; NV_PN: 131-0653-000; PACK_TYPE: SMD_9X8; PATH: I35; PHYS_PAGE: 28; PLACEMENT_NOTE: CoLayout with L16; Q: [ ]@[ ]; ROT: 0; SEC: 1; SEC_TYPE: SMD_9X8; SELF_RESONANCE_FREQ: [ ]; SIGNAL_MODEL: nv_ind; SKU: NO STUFF; TOL: 20%; VER: 1; XY: (-4300,3650)
L16 = L: ACOUSTIC_MARGIN: [ ]; ASSEMBLY: VR_5V; CDS_LIB: discrete; CDS_PART_NAME: L_SMD_073X066-1UH,CARBONYL POWDER,20%,11A,22A,0.01OHM,[ ]@[ ],[ ],[ ],130-0776-000; CDS_PHYS_PART_NAME: L_SMD_073X066-1UH,CARBONYL POWDER,20%,11A,22A,0.01OHM,[ ]@[ ],[ ],[ ],130-0776-000-130-0776-000,1UH; CDS_SEC: 1; CONTINUOUS_CURRENT: 11A; DC_RESISTANCE: 0.01ohm; DEVICE_TYPENAME: L_SMD_073X066-1UHCARBONYLPOWDER2011A22A001OHM130-0776-000-130-0776-0001UH; DRAWING: @P2597_C02_LIB.P2597_C02(SCH_1):PAGE28; MAT: Carbonyl Powder; MAX_CURRENT: 22A; NV_PN: 130-0776-000; PACK_TYPE: SMD_073X066; PATH: I208; PHYS_PAGE: 28; PLACEMENT_NOTE: CoLayout with L15; Q: [ ]@[ ]; ROT: 0; SEC: 1; SEC_TYPE: SMD_073X066; SELF_RESONANCE_FREQ: [ ]; SIGNAL_MODEL: nv_ind; TOL: 20%; VER: 1; XY: (-4300,3350)
Q23 = Q_FET_N_ENH#4: ASSEMBLY: VR_3V3; CDS_LIB: discrete; CDS_PART_NAME: Q_FET_N_ENH_WPAK_DUAL_COPAD-SIZ918DT-T1-GE3,30V / 30V,12MOHM,3.7MOHM@10V / 14.5MOHM,4.5MOHM@4.5V / -1000MOHM,-1000MOHM@2.5V,14A; CDS_PHYS_PART_NAME: Q_FET_N_ENH_WPAK_DUAL_COPAD-SIZ918DT-T1-GE3,30V / 30V,12MOHM,3.7MOHM@10V / 14.5MOHM,4.5MOHM@4.5V / -1000MOHM,-1000MOHM@2.5V,14B; CDS_SEC: 1; CONTINUOUS_CURRENT: 14.3A / 26A; DEVICE_TYPENAME: Q_FET_N_ENH_WPAK_DUAL_COPAD-SIZ918DT-T1-GE330V30V12MOHM37MOHM10V145MOHM45MOHM45V-1000MOHM-1000MOHM25V14B; DRAWING: @P2597_C02_LIB.P2597_C02(SCH_1):PAGE28; MAX_CURRENT: 50A / 110A; MAX_VOLTAGE: 30V / 30V; MAX_WATTAGE: 4.2W / 4.2W; NV_NAME: SiZ918DT-T1-GE3; NV_PN: 300-0785-000; PACK_TYPE: WPAK_DUAL_COPAD; PATH: I281; PHYS_PAGE: 28; Q_G: [ ],[ ]@10V / [ ],[ ]@4.5V / [ ],[ ]@2.5V; ROT: 0; R_DS_ON: 12mohm,3.7mohm@10V / 14.5mohm,4.5mohm@4.5V / -1000mohm,-1000mohm@2.5V; SEC: 1; SEC_TYPE: WPAK_DUAL_COPAD; VER: 15; V_BE_GS: 20V / 20V; XY: (-5650,50)
Q29 = Q_FET_N_ENH#4: ASSEMBLY: VR_5V; CDS_LIB: discrete; CDS_PART_NAME: Q_FET_N_ENH_WPAK_DUAL_COPAD-SIZ918DT-T1-GE3,30V / 30V,12MOHM,3.7MOHM@10V / 14.5MOHM,4.5MOHM@4.5V / -1000MOHM,-1000MOHM@2.5V,14A; CDS_PHYS_PART_NAME: Q_FET_N_ENH_WPAK_DUAL_COPAD-SIZ918DT-T1-GE3,30V / 30V,12MOHM,3.7MOHM@10V / 14.5MOHM,4.5MOHM@4.5V / -1000MOHM,-1000MOHM@2.5V,14B; CDS_SEC: 1; CONTINUOUS_CURRENT: 14.3A / 26A; DEVICE_TYPENAME: Q_FET_N_ENH_WPAK_DUAL_COPAD-SIZ918DT-T1-GE330V30V12MOHM37MOHM10V145MOHM45MOHM45V-1000MOHM-1000MOHM25V14B; DRAWING: @P2597_C02_LIB.P2597_C02(SCH_1):PAGE28; MAX_CURRENT: 50A / 110A; MAX_VOLTAGE: 30V / 30V; MAX_WATTAGE: 4.2W / 4.2W; NV_NAME: SiZ918DT-T1-GE3; NV_PN: 300-0785-000; PACK_TYPE: WPAK_DUAL_COPAD; PATH: I271; PHYS_PAGE: 28; Q_G: [ ],[ ]@10V / [ ],[ ]@4.5V / [ ],[ ]@2.5V; ROT: 0; R_DS_ON: 12mohm,3.7mohm@10V / 14.5mohm,4.5mohm@4.5V / -1000mohm,-1000mohm@2.5V; SEC: 1; SEC_TYPE: WPAK_DUAL_COPAD; VER: 15; V_BE_GS: 20V / 20V; XY: (-5650,3450)
Q501 = Q_FET_N_ENH: ASSEMBLY: VR_5V; CDS_LIB: discrete; CDS_PART_NAME: Q_FET_N_ENH_SOT23_6D_1G1D1S-AO6800,30V,-1000MOHM@10V / 75MOHM@4.5V / 115MOHM@2.5V,3.4A,20A,12V,1.15W,[ ]@10V / [ ]@4.5V / [ ]@A; CDS_PHYS_PART_NAME: Q_FET_N_ENH_SOT23_6D_1G1D1S-AO6800,30V,-1000MOHM@10V / 75MOHM@4.5V / 115MOHM@2.5V,3.4A,20A,12V,1.15W,[ ]@10V / [ ]@4.5V / [ ]@B; CDS_SEC: 2; CONTINUOUS_CURRENT: 3.4A; DEVICE_TYPENAME: Q_FET_N_ENH_SOT23_6D_1G1D1S-AO680030V-1000MOHM10V75MOHM45V115MOHM25V34A20A12V115W10V45VB; DRAWING: @P2597_C02_LIB.P2597_C02(SCH_1):PAGE28; MAX_CURRENT: 20A; MAX_VOLTAGE: 30V; MAX_WATTAGE: 1.15W; NV_NAME: AO6800; NV_PN: 300-0634-000; PACK_TYPE: SOT23_6D_1G1D1S; PATH: I189; PHYS_PAGE: 28; Q_G: [ ]@10V / [ ]@4.5V / [ ]@2.5V; ROT: 0; R_DS_ON: -1000mohm@10V / 75mohm@4.5V / 115mohm@2.5V; SEC: 2; SEC_TYPE: SOT23_6D_1G1D1S; VER: 2; V_BE_GS: 12V; XY: (-10400,2850)
Q502 = Q_FET_N_ENH#2: ASSEMBLY: CONN_POWER; CDS_LIB: discrete; CDS_PART_NAME: Q_FET_N_ENH_SOT323_1G1D1S-NTS4001NT1G,30V,1500MOHM@10V / 1500MOHM@4.5V / 1500MOHM@2.5V,0.27A,0.8A,20V,0.33W,[ ]@10V / [ ]@4.5VA; CDS_PHYS_PART_NAME: Q_FET_N_ENH_SOT323_1G1D1S-NTS4001NT1G,30V,1500MOHM@10V / 1500MOHM@4.5V / 1500MOHM@2.5V,0.27A,0.8A,20V,0.33W,[ ]@10V / [ ]@4.5VB; CDS_SEC: 1; CONTINUOUS_CURRENT: 0.27A; CaptureCellPackProp: Q_FET_N_ENH__sym_2##2; DEVICE_TYPENAME: Q_FET_N_ENH_SOT323_1G1D1S-NTS4001NT1G30V1500MOHM10V1500MOHM45V1500MOHM25V027A08A20V033W10V45VB; DRAWING: @P2597_C02_LIB.P2597_C02(SCH_1):PAGE28; MAX_CURRENT: 0.8A; MAX_VOLTAGE: 30V; MAX_WATTAGE: 0.33W; NV_NAME: NTS4001NT1G; NV_PN: 300-0485-000; PACK_TYPE: SOT323_1G1D1S; PATH: I230; PHYS_PAGE: 28; Q_G: [ ]@10V / [ ]@4.5V / [ ]@2.5V; ROT: 0; R_DS_ON: 1500mohm@10V / 1500mohm@4.5V / 1500mohm@2.5V; SEC: 1; SEC_TYPE: SOT323_1G1D1S; VER: 2; V_BE_GS: 20V; XY: (-10000,-1100)
Q503 = Q_FET_N_ENH#2: ASSEMBLY: VR_3V3; CDS_LIB: discrete; CDS_PART_NAME: Q_FET_N_ENH_SOT23_1G1D1S-FDV301N,25V,-1000MOHM@10V / 4000MOHM@4.5V / -1000MOHM@2.5V,0.22A,0.5A,8V,0.35W,[ ]@10V / [ ]@4.5V / [A; CDS_PHYS_PART_NAME: Q_FET_N_ENH_SOT23_1G1D1S-FDV301N,25V,-1000MOHM@10V / 4000MOHM@4.5V / -1000MOHM@2.5V,0.22A,0.5A,8V,0.35W,[ ]@10V / [ ]@4.5V / [B; CDS_SEC: 1; CONTINUOUS_CURRENT: 0.22A; CaptureCellPackProp: Q_FET_N_ENH__sym_2##2; DEVICE_TYPENAME: Q_FET_N_ENH_SOT23_1G1D1S-FDV301N25V-1000MOHM10V4000MOHM45V-1000MOHM25V022A05A8V035W10V45VB; DRAWING: @P2597_C02_LIB.P2597_C02(SCH_1):PAGE28; MAX_CURRENT: 0.5A; MAX_VOLTAGE: 25V; MAX_WATTAGE: 0.35W; NV_NAME: FDV301N; NV_PN: 300-0494-000; PACK_TYPE: SOT23_1G1D1S; PATH: I209; PHYS_PAGE: 28; Q_G: [ ]@10V / [ ]@4.5V / [ ]@2.5V; ROT: 0; R_DS_ON: -1000mohm@10V / 4000mohm@4.5V / -1000mohm@2.5V; SEC: 1; VER: 2; V_BE_GS: 8V; XY: (-10100,50)
R138 = R_SENSE_4PIN: ASSEMBLY: VR_3V3; CDS_LIB: discrete; CDS_PART_NAME: R_SENSE_4PIN_R_SENSE_4PIN-0.01OHM,1%,1W,[ ],215-0142-000; CDS_PHYS_PART_NAME: R_SENSE_4PIN_R_SENSE_4PIN-0.01OHM,1%,1W,[ ],215-0142-000-0.01OHM,215-0142-000; CDS_SEC: 1; DEVICE_TYPENAME: R_SENSE_4PIN_R_SENSE_4PIN-001OHM11W215-0142-000-001OHM215-0142-000; DRAWING: @P2597_C02_LIB.P2597_C02(SCH_1):PAGE28; MAX_WATTAGE: 1W; NV_PN: 215-0142-000; PATH: I182; PHYS_PAGE: 28; ROT: 2; SEC: 1; SIGNAL_MODEL: nv_res_sense_4p_noxnet; TEMP_COEF: [ ]; TOL: 1%; VER: 1; XY: (-450,100)
R159 = R#1: ASSEMBLY: VR_3V3; CDS_LIB: discrete; CDS_PART_NAME: R_0603-10OHM,1 %,0.1W,195-0651-000; CDS_PHYS_PART_NAME: R_0603-10OHM,1 %,0.1W,195-0651-000-10OHM,195-0651-000; CDS_SEC: 1; CHIPS_PART_NAME: R; DEVICE_TYPENAME: R_0603-10OHM101W195-0651-000-10OHM195-0651-000; DRAWING: @P2597_C02_LIB.P2597_C02(SCH_1):PAGE28; MAX_WATTAGE: 0.1W; NV_PN: 195-0651-000; PATH: I131; PHYS_PAGE: 28; ROT: 0; SEC: 1; SIGNAL_MODEL: nv_res; TOL: 1%; VER: 2; XY: (-3650,-200)
R161 = R#1: ASSEMBLY: VR_3V3; CDS_LIB: discrete; CDS_PART_NAME: R_0402-1K,5 %,62.5MW,195-0485-000; CDS_PHYS_PART_NAME: R_0402-1K,5 %,62.5MW,195-0485-000-195-0485-000,1K; CDS_SEC: 1; CHIPS_PART_NAME: R; DEVICE_TYPENAME: R_0402-1K5625MW195-0485-000-195-0485-0001K; DRAWING: @P2597_C02_LIB.P2597_C02(SCH_1):PAGE28; MAX_WATTAGE: 62.5mW; NV_PN: 195-0485-000; PATH: I213; PHYS_PAGE: 28; ROT: 0; SEC: 1; SIGNAL_MODEL: nv_res; TOL: 5%; VER: 2; XY: (-3300,-700)
R162 = R#1: ASSEMBLY: VR_3V3; CDS_LIB: discrete; CDS_PART_NAME: R_0402-71.5K,1 %,62.5MW,195-0415-000; CDS_PHYS_PART_NAME: R_0402-71.5K,1 %,62.5MW,195-0415-000-195-0415-000,71.5K; CDS_SEC: 1; CHIPS_PART_NAME: R; DEVICE_TYPENAME: R_0402-715K1625MW195-0415-000-195-0415-000715K; DRAWING: @P2597_C02_LIB.P2597_C02(SCH_1):PAGE28; MAX_WATTAGE: 62.5mW; NV_PN: 195-0415-000; PATH: I136; PHYS_PAGE: 28; ROT: 0; SEC: 1; SIGNAL_MODEL: nv_res; TOL: 1%; VER: 2; XY: (-3650,-700)
R166 = R#1: ASSEMBLY: VR_3V3; CDS_LIB: discrete; CDS_PART_NAME: R_0402-21.5K,1 %,62.5MW,195-0165-000; CDS_PHYS_PART_NAME: R_0402-21.5K,1 %,62.5MW,195-0165-000-195-0165-000,21.5K; CDS_SEC: 1; CHIPS_PART_NAME: R; DEVICE_TYPENAME: R_0402-215K1625MW195-0165-000-195-0165-000215K; DRAWING: @P2597_C02_LIB.P2597_C02(SCH_1):PAGE28; MAX_WATTAGE: 62.5mW; NV_PN: 195-0165-000; PATH: I137; PHYS_PAGE: 28; ROT: 0; SEC: 1; SIGNAL_MODEL: nv_res; TOL: 1%; VER: 2; XY: (-3650,-1350)
R225 = R_SENSE_4PIN: ASSEMBLY: VR_5V; CDS_LIB: discrete; CDS_PART_NAME: R_SENSE_4PIN_R_SENSE_4PIN-0.005OHM,1%,1W,[ ],215-0164-000; CDS_PHYS_PART_NAME: R_SENSE_4PIN_R_SENSE_4PIN-0.005OHM,1%,1W,[ ],215-0164-000-0.005OHM,215-0164-000; CDS_SEC: 1; DEVICE_TYPENAME: R_SENSE_4PIN_R_SENSE_4PIN-0005OHM11W215-0164-000-0005OHM215-0164-000; DRAWING: @P2597_C02_LIB.P2597_C02(SCH_1):PAGE28; MAX_WATTAGE: 1W; NV_PN: 215-0164-000; PATH: I211; PHYS_PAGE: 28; ROT: 2; SEC: 1; SIGNAL_MODEL: nv_res_sense_4p_noxnet; TEMP_COEF: [ ]; TOL: 1%; VER: 1; XY: (-400,3350)
R243 = R#1: ASSEMBLY: VR_5V; CDS_LIB: discrete; CDS_PART_NAME: R_0603-10OHM,1 %,0.1W,195-0651-000; CDS_PHYS_PART_NAME: R_0603-10OHM,1 %,0.1W,195-0651-000-10OHM,195-0651-000; CDS_SEC: 1; CHIPS_PART_NAME: R; DEVICE_TYPENAME: R_0603-10OHM101W195-0651-000-10OHM195-0651-000; DRAWING: @P2597_C02_LIB.P2597_C02(SCH_1):PAGE28; MAX_WATTAGE: 0.1W; NV_PN: 195-0651-000; PATH: I44; PHYS_PAGE: 28; ROT: 0; SEC: 1; SIGNAL_MODEL: nv_res; TOL: 1%; VER: 2; XY: (-3700,3100)
R250 = R#1: ASSEMBLY: VR_5V; CDS_LIB: discrete; CDS_PART_NAME: R_0402-1K,5 %,62.5MW,195-0485-000; CDS_PHYS_PART_NAME: R_0402-1K,5 %,62.5MW,195-0485-000-195-0485-000,1K; CDS_SEC: 1; CHIPS_PART_NAME: R; DEVICE_TYPENAME: R_0402-1K5625MW195-0485-000-195-0485-0001K; DRAWING: @P2597_C02_LIB.P2597_C02(SCH_1):PAGE28; MAX_WATTAGE: 62.5mW; NV_PN: 195-0485-000; PATH: I212; PHYS_PAGE: 28; ROT: 0; SEC: 1; SIGNAL_MODEL: nv_res; TOL: 5%; VER: 2; XY: (-3350,2550)
R251 = R#1: ASSEMBLY: VR_5V; CDS_LIB: discrete; CDS_PART_NAME: R_0402-121K,1 %,62.5MW,195-0046-000; CDS_PHYS_PART_NAME: R_0402-121K,1 %,62.5MW,195-0046-000-121K,195-0046-000; CDS_SEC: 1; CHIPS_PART_NAME: R; DEVICE_TYPENAME: R_0402-121K1625MW195-0046-000-121K195-0046-000; DRAWING: @P2597_C02_LIB.P2597_C02(SCH_1):PAGE28; MAX_WATTAGE: 62.5mW; NV_PN: 195-0046-000; PATH: I39; PHYS_PAGE: 28; ROT: 0; SEC: 1; SIGNAL_MODEL: DEFAULT_RESISTOR_4750OHM_2_1; TOL: 1%; VER: 2; XY: (-3700,2550)
R256 = R#1: ASSEMBLY: VR_5V; CDS_LIB: discrete; CDS_PART_NAME: R_0402-22.1K,1 %,62.5MW,195-0170-000; CDS_PHYS_PART_NAME: R_0402-22.1K,1 %,62.5MW,195-0170-000-195-0170-000,22.1K; CDS_SEC: 1; CHIPS_PART_NAME: R; DEVICE_TYPENAME: R_0402-221K1625MW195-0170-000-195-0170-000221K; DRAWING: @P2597_C02_LIB.P2597_C02(SCH_1):PAGE28; MAX_WATTAGE: 62.5mW; NV_PN: 195-0170-000; PATH: I38; PHYS_PAGE: 28; ROT: 0; SEC: 1; SIGNAL_MODEL: DEFAULT_RESISTOR_649OHM_2_1; TOL: 1%; VER: 2; XY: (-3700,1900)
R502 = R#1: ASSEMBLY: VR_3V3; CDS_LIB: discrete; CDS_PART_NAME: R_0402-1M,5 %,62.5MW,195-0488-000; CDS_PHYS_PART_NAME: R_0402-1M,5 %,62.5MW,195-0488-000-195-0488-000,1M; CDS_SEC: 1; CHIPS_PART_NAME: R; DEVICE_TYPENAME: R_0402-1M5625MW195-0488-000-195-0488-0001M; DRAWING: @P2597_C02_LIB.P2597_C02(SCH_1):PAGE28; MAX_WATTAGE: 62.5mW; NV_PN: 195-0488-000; PATH: I201; PHYS_PAGE: 28; ROT: 0; SEC: 1; SIGNAL_MODEL: nv_res; TOL: 5%; VER: 2; XY: (-10500,-250)
R503 = R#1: ASSEMBLY: VR_5V; CDS_LIB: discrete; CDS_PART_NAME: R_0402-47K,5 %,62.5MW,195-0599-000; CDS_PHYS_PART_NAME: R_0402-47K,5 %,62.5MW,195-0599-000-195-0599-000,47K; CDS_SEC: 1; CHIPS_PART_NAME: R; DEVICE_TYPENAME: R_0402-47K5625MW195-0599-000-195-0599-00047K; DRAWING: @P2597_C02_LIB.P2597_C02(SCH_1):PAGE28; MAX_WATTAGE: 62.5mW; NV_PN: 195-0599-000; PATH: I194; PHYS_PAGE: 28; ROT: 0; SEC: 1; SIGNAL_MODEL: nv_res; TOL: 5%; VER: 2; XY: (-10300,3600)
R504 = R#1: ASSEMBLY: VR_5V; CDS_LIB: discrete; CDS_PART_NAME: R_0402-10K,5 %,62.5MW,195-0486-000; CDS_PHYS_PART_NAME: R_0402-10K,5 %,62.5MW,195-0486-000-10K,195-0486-000; CDS_SEC: 1; CHIPS_PART_NAME: R; DEVICE_TYPENAME: R_0402-10K5625MW195-0486-000-10K195-0486-000; DRAWING: @P2597_C02_LIB.P2597_C02(SCH_1):PAGE28; MAX_WATTAGE: 62.5mW; NV_PN: 195-0486-000; PATH: I191; PHYS_PAGE: 28; ROT: 0; SEC: 1; SIGNAL_MODEL: DEFAULT_RESISTOR_10000OHM_2_1; TOL: 5%; VER: 2; XY: (-10750,3600)
R505 = R#1: ASSEMBLY: VR_5V; CDS_LIB: discrete; CDS_PART_NAME: R_0402-1M,5 %,62.5MW,195-0488-000; CDS_PHYS_PART_NAME: R_0402-1M,5 %,62.5MW,195-0488-000-195-0488-000,1M; CDS_SEC: 1; CHIPS_PART_NAME: R; DEVICE_TYPENAME: R_0402-1M5625MW195-0488-000-195-0488-0001M; DRAWING: @P2597_C02_LIB.P2597_C02(SCH_1):PAGE28; MAX_WATTAGE: 62.5mW; NV_PN: 195-0488-000; PATH: I203; PHYS_PAGE: 28; ROT: 0; SEC: 1; SIGNAL_MODEL: nv_res; TOL: 5%; VER: 2; XY: (-10650,2550)
R506 = R: ASSEMBLY: VR_5V; CDS_LIB: discrete; CDS_PART_NAME: R_0402-10K,5 %,62.5MW,195-0486-000; CDS_PHYS_PART_NAME: R_0402-10K,5 %,62.5MW,195-0486-000-10K,195-0486-000; CDS_SEC: 1; DEVICE_TYPENAME: R_0402-10K5625MW195-0486-000-10K195-0486-000; DRAWING: @P2597_C02_LIB.P2597_C02(SCH_1):PAGE28; MAX_WATTAGE: 62.5mW; NV_PN: 195-0486-000; PATH: I9; PHYS_PAGE: 28; ROT: 0; SEC: 1; SIGNAL_MODEL: DEFAULT_RESISTOR_10000OHM_2_1; SKU: NO STUFF; TOL: 5%; VER: 1; XY: (-8500,3600)
R507 = R: ASSEMBLY: VR_5V; CDS_LIB: discrete; CDS_PART_NAME: R_0402-0OHM,0.05 OHM,62.5MW,195-2655-000; CDS_PHYS_PART_NAME: R_0402-0OHM,0.05 OHM,62.5MW,195-2655-000-0OHM,195-2655-000; CDS_SEC: 1; DEVICE_TYPENAME: R_0402-0OHM005OHM625MW195-2655-000-0OHM195-2655-000; DRAWING: @P2597_C02_LIB.P2597_C02(SCH_1):PAGE28; MAX_WATTAGE: 62.5mW; NV_PN: 195-2655-000; PATH: I217; PHYS_PAGE: 28; ROT: 0; SEC: 1; SIGNAL_MODEL: nv_res; TOL: 0.05 ohm; VER: 1; XY: (-10250,4150)
R508 = R: ASSEMBLY: VR_5V; CDS_LIB: discrete; CDS_PART_NAME: R_0402-0OHM,0.05 OHM,62.5MW,195-2655-000; CDS_PHYS_PART_NAME: R_0402-0OHM,0.05 OHM,62.5MW,195-2655-000-0OHM,195-2655-000; CDS_SEC: 1; DEVICE_TYPENAME: R_0402-0OHM005OHM625MW195-2655-000-0OHM195-2655-000; DRAWING: @P2597_C02_LIB.P2597_C02(SCH_1):PAGE28; MAX_WATTAGE: 62.5mW; NV_PN: 195-2655-000; PATH: I222; PHYS_PAGE: 28; ROT: 0; SEC: 1; SIGNAL_MODEL: nv_res; SKU: NO STUFF; TOL: 0.05 ohm; VER: 1; XY: (-7700,1750)
R509 = R#1: ASSEMBLY: VR_3V3; CDS_LIB: discrete; CDS_PART_NAME: R_0402-10K,5 %,62.5MW,195-0486-000; CDS_PHYS_PART_NAME: R_0402-10K,5 %,62.5MW,195-0486-000-10K,195-0486-000; CDS_SEC: 1; CHIPS_PART_NAME: R; DEVICE_TYPENAME: R_0402-10K5625MW195-0486-000-10K195-0486-000; DRAWING: @P2597_C02_LIB.P2597_C02(SCH_1):PAGE28; MAX_WATTAGE: 62.5mW; NV_PN: 195-0486-000; PATH: I220; PHYS_PAGE: 28; ROT: 0; SEC: 1; SIGNAL_MODEL: DEFAULT_RESISTOR_10000OHM_2_1; TOL: 5%; VER: 2; XY: (-9200,2200)
R510 = R: ASSEMBLY: VR_3V3; CDS_LIB: discrete; CDS_PART_NAME: R_0402-0OHM,0.05 OHM,62.5MW,195-2655-000; CDS_PHYS_PART_NAME: R_0402-0OHM,0.05 OHM,62.5MW,195-2655-000-0OHM,195-2655-000; CDS_SEC: 1; DEVICE_TYPENAME: R_0402-0OHM005OHM625MW195-2655-000-0OHM195-2655-000; DRAWING: @P2597_C02_LIB.P2597_C02(SCH_1):PAGE28; MAX_WATTAGE: 62.5mW; NV_PN: 195-2655-000; PATH: I221; PHYS_PAGE: 28; ROT: 0; SEC: 1; SIGNAL_MODEL: nv_res; TOL: 0.05 ohm; VER: 1; XY: (-7700,1950)
R511 = R: ASSEMBLY: VR_5V; CDS_LIB: discrete; CDS_PART_NAME: R_0402-0OHM,0.05 OHM,62.5MW,195-2655-000; CDS_PHYS_PART_NAME: R_0402-0OHM,0.05 OHM,62.5MW,195-2655-000-0OHM,195-2655-000; CDS_SEC: 1; DEVICE_TYPENAME: R_0402-0OHM005OHM625MW195-2655-000-0OHM195-2655-000; DRAWING: @P2597_C02_LIB.P2597_C02(SCH_1):PAGE28; MAX_WATTAGE: 62.5mW; NV_PN: 195-2655-000; PATH: I224; PHYS_PAGE: 28; ROT: 0; SEC: 1; SIGNAL_MODEL: nv_res; TOL: 0.05 ohm; VER: 1; XY: (-7700,1550)
R512 = R#1: ASSEMBLY: VR_5V; CDS_LIB: discrete; CDS_PART_NAME: R_0603-3.3OHM,5 %,0.1W,195-1217-000; CDS_PHYS_PART_NAME: R_0603-3.3OHM,5 %,0.1W,195-1217-000-195-1217-000,3.3OHM; CDS_SEC: 1; CHIPS_PART_NAME: R; DEVICE_TYPENAME: R_0603-33OHM501W195-1217-000-195-1217-00033OHM; DRAWING: @P2597_C02_LIB.P2597_C02(SCH_1):PAGE28; MAX_WATTAGE: 0.1W; NV_PN: 195-1217-000; PATH: I28; PHYS_PAGE: 28; ROT: 0; SEC: 1; SIGNAL_MODEL: nv_res; TOL: 5%; VER: 2; XY: (-6500,2850)
R513 = R#1: ASSEMBLY: VR_3V3; CDS_LIB: discrete; CDS_PART_NAME: R_0402-10K,5 %,62.5MW,195-0486-000; CDS_PHYS_PART_NAME: R_0402-10K,5 %,62.5MW,195-0486-000-10K,195-0486-000; CDS_SEC: 1; CHIPS_PART_NAME: R; DEVICE_TYPENAME: R_0402-10K5625MW195-0486-000-10K195-0486-000; DRAWING: @P2597_C02_LIB.P2597_C02(SCH_1):PAGE28; MAX_WATTAGE: 62.5mW; NV_PN: 195-0486-000; PATH: I157; PHYS_PAGE: 28; ROT: 0; SEC: 1; SIGNAL_MODEL: DEFAULT_RESISTOR_10000OHM_2_1; TOL: 5%; VER: 2; XY: (-7750,-1550)
R514 = R#1: ASSEMBLY: VR_5V; CDS_LIB: discrete; CDS_PART_NAME: R_0402-75K,5 %,62.5MW,195-0634-000; CDS_PHYS_PART_NAME: R_0402-75K,5 %,62.5MW,195-0634-000-195-0634-000,75K; CDS_SEC: 1; CHIPS_PART_NAME: R; DEVICE_TYPENAME: R_0402-75K5625MW195-0634-000-195-0634-00075K; DRAWING: @P2597_C02_LIB.P2597_C02(SCH_1):PAGE28; MAX_WATTAGE: 62.5mW; NV_PN: 195-0634-000; PATH: I25; PHYS_PAGE: 28; ROT: 0; SEC: 1; SIGNAL_MODEL: DEFAULT_RESISTOR_22100OHM_2_1; TOL: 5%; VER: 2; XY: (-6150,2650)
R515 = R: ASSEMBLY: VR_5V; CDS_LIB: discrete; CDS_PART_NAME: R_0402-1OHM,5 %,62.5MW,195-0482-000; CDS_PHYS_PART_NAME: R_0402-1OHM,5 %,62.5MW,195-0482-000-195-0482-000,1OHM; CDS_SEC: 1; DEVICE_TYPENAME: R_0402-1OHM5625MW195-0482-000-195-0482-0001OHM; DRAWING: @P2597_C02_LIB.P2597_C02(SCH_1):PAGE28; MAX_WATTAGE: 62.5mW; NV_PN: 195-0482-000; PATH: I27; PHYS_PAGE: 28; ROT: 0; SEC: 1; SIGNAL_MODEL: DEFAULT_RESISTOR_1OHM_2_1; TOL: 5%; VER: 1; XY: (-6750,3800)
R522 = R: ASSEMBLY: VR_3V3; CDS_LIB: discrete; CDS_PART_NAME: R_0402-10K,5 %,62.5MW,195-0486-000; CDS_PHYS_PART_NAME: R_0402-10K,5 %,62.5MW,195-0486-000-10K,195-0486-000; CDS_SEC: 1; DEVICE_TYPENAME: R_0402-10K5625MW195-0486-000-10K195-0486-000; DRAWING: @P2597_C02_LIB.P2597_C02(SCH_1):PAGE28; MAX_WATTAGE: 62.5mW; NV_PN: 195-0486-000; PATH: I151; PHYS_PAGE: 28; ROT: 0; SEC: 1; SIGNAL_MODEL: DEFAULT_RESISTOR_10000OHM_2_1; SKU: NO STUFF; TOL: 5%; VER: 1; XY: (-8450,350)
R533 = R#1: ASSEMBLY: VR_3V3; CDS_LIB: discrete; CDS_PART_NAME: R_0603-3.3OHM,5 %,0.1W,195-1217-000; CDS_PHYS_PART_NAME: R_0603-3.3OHM,5 %,0.1W,195-1217-000-195-1217-000,3.3OHM; CDS_SEC: 1; CHIPS_PART_NAME: R; DEVICE_TYPENAME: R_0603-33OHM501W195-1217-000-195-1217-00033OHM; DRAWING: @P2597_C02_LIB.P2597_C02(SCH_1):PAGE28; MAX_WATTAGE: 0.1W; NV_PN: 195-1217-000; PATH: I142; PHYS_PAGE: 28; ROT: 0; SEC: 1; SIGNAL_MODEL: nv_res; TOL: 5%; VER: 2; XY: (-6450,-400)
R535 = R#1: ASSEMBLY: VR_3V3; CDS_LIB: discrete; CDS_PART_NAME: R_0402-75K,5 %,62.5MW,195-0634-000; CDS_PHYS_PART_NAME: R_0402-75K,5 %,62.5MW,195-0634-000-195-0634-000,75K; CDS_SEC: 1; CHIPS_PART_NAME: R; DEVICE_TYPENAME: R_0402-75K5625MW195-0634-000-195-0634-00075K; DRAWING: @P2597_C02_LIB.P2597_C02(SCH_1):PAGE28; MAX_WATTAGE: 62.5mW; NV_PN: 195-0634-000; PATH: I144; PHYS_PAGE: 28; ROT: 0; SEC: 1; SIGNAL_MODEL: DEFAULT_RESISTOR_22100OHM_2_1; TOL: 5%; VER: 2; XY: (-6100,-600)
R536 = R: ASSEMBLY: VR_3V3; CDS_LIB: discrete; CDS_PART_NAME: R_0402-1OHM,5 %,62.5MW,195-0482-000; CDS_PHYS_PART_NAME: R_0402-1OHM,5 %,62.5MW,195-0482-000-195-0482-000,1OHM; CDS_SEC: 1; DEVICE_TYPENAME: R_0402-1OHM5625MW195-0482-000-195-0482-0001OHM; DRAWING: @P2597_C02_LIB.P2597_C02(SCH_1):PAGE28; MAX_WATTAGE: 62.5mW; NV_PN: 195-0482-000; PATH: I148; PHYS_PAGE: 28; ROT: 0; SEC: 1; SIGNAL_MODEL: DEFAULT_RESISTOR_1OHM_2_1; TOL: 5%; VER: 1; XY: (-6700,550)
U16 = U_SWREG_TPS53015: ASSEMBLY: VR_3V3; CDS_LIB: power_supply; CDS_PART_NAME: U_SWREG_TPS53015_XSOP10-TPS53015,BUCK,1PH,500KHZ,NONE,0.77V..7V,1%,0.773V,28V,10A,50W,316-0314-000; CDS_PHYS_PART_NAME: U_SWREG_TPS53015_XSOP10-TPS53015,BUCK,1PH,500KHZ,NONE,0.77V..7V,1%,0.773V,28V,10A,50W,316-0314-000-0.773V,316-0314-000; CDS_SEC: 1; DEVICE_TYPENAME: U_SWREG_TPS53015_XSOP10-TPS53015BUCK1PH500KHZNONE077V7V10773V28V10A50W316-0314-000-0773V316-0314-000; DRAWING: @P2597_C02_LIB.P2597_C02(SCH_1):PAGE28; MAX_CURRENT: 10A; MAX_VOLTAGE: 28V; MAX_WATTAGE: 50W; MODE: Buck; NV_NAME: TPS53015; NV_PN: 316-0314-000; OUTPUT_VOLTAGE: 0.77V..7V; PACK_TYPE: XSOP10; PATH: I150; PHASES: 1Ph; PHYS_PAGE: 28; PROGRAMMABLE: None; ROT: 0; SEC: 1; SEC_TYPE: XSOP10; SWITCHING_FREQ: 500KHz; TOL: 1%; VER: 1; XY: (-7300,0)
U31 = U_SWREG_TPS53015: ASSEMBLY: VR_5V; CDS_LIB: power_supply; CDS_PART_NAME: U_SWREG_TPS53015_XSOP10-TPS53015,BUCK,1PH,500KHZ,NONE,0.77V..7V,1%,0.773V,28V,10A,50W,316-0314-000; CDS_PHYS_PART_NAME: U_SWREG_TPS53015_XSOP10-TPS53015,BUCK,1PH,500KHZ,NONE,0.77V..7V,1%,0.773V,28V,10A,50W,316-0314-000-0.773V,316-0314-000; CDS_SEC: 1; DEVICE_TYPENAME: U_SWREG_TPS53015_XSOP10-TPS53015BUCK1PH500KHZNONE077V7V10773V28V10A50W316-0314-000-0773V316-0314-000; DRAWING: @P2597_C02_LIB.P2597_C02(SCH_1):PAGE28; MAX_CURRENT: 10A; MAX_VOLTAGE: 28V; MAX_WATTAGE: 50W; MODE: Buck; NV_NAME: TPS53015; NV_PN: 316-0314-000; OUTPUT_VOLTAGE: 0.77V..7V; PACK_TYPE: XSOP10; PATH: I26; PHASES: 1Ph; PHYS_PAGE: 28; PROGRAMMABLE: None; ROT: 0; SEC: 1; SEC_TYPE: XSOP10; SWITCHING_FREQ: 500KHz; TOL: 1%; VER: 1; XY: (-7350,3250)

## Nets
1V8_IO_VREG_EN: R508.2 R511.2 ; also on sheet 5
3V3_SYS_BUCK_EN: C119.1 Q503.3(D) R510.2 R522.1 U16.4(EN)
GND: C76.2 C85.2 C86.2 C88.2 C90.2 C106.2 C107.2 C119.2 C120.2 C125.2 C126.2 C142.2 C143.2 C144.2 C148.2 C149.2 C154.2 C156.2 C158.2 C163.2 C164.2 C165.2 C170.2 C171.2 C172.2 C173.2 C502.2 C503.2 C508.2 Q23.3(S1) Q23.4(S2) Q23.5(S3) Q29.3(S1) Q29.4(S2) Q29.5(S3) Q501.2(S) Q501.5(S) Q502.2(S) Q503.2(S) R166.2 R256.2 R502.2 R505.2 R514.2 R535.2 U16.6(PGND) U31.6(PGND) ; also on sheet 1 2 3 4 5 7 9 10 11 12 13 14 15 16 17 18 19 20 21 22 23 24 25 26 30
VDD_3V3_SYS: R138.1 R513.1 ; also on sheet 1 2 3 4 5 12 13 17 18 19 23 24 25
VDD_3V3_SYS_N: R138.2 ; also on sheet 3
VDD_3V3_SYS_P: R138.3 ; also on sheet 3
VDD_3V3_SYS_PG: R511.1 R513.2 U16.2(PG) ; also on sheet 1
VDD_3V3_SYS_PWR_R: C76.1 C85.1 C86.1 C88.1 C90.1 L7.2 L8.2 L9.2 R138.4 R159.1
VDD_5V0_IO_SYS: R225.1 R503.1 R504.1 R509.1 ; also on sheet 4 5 9 11 12 16 17 18 20 22 26 30
VDD_5V0_IO_SYS_PG: R508.1 R509.2 R510.1 U31.2(PG)
VDD_5V0_IO_SYS_R: C142.1 C143.1 C144.1 C148.1 C149.1 C154.1 C156.1 C158.1 L15.2 L16.2 R225.4 R243.1
VDD_5V_IO_SYS_N: R225.2 ; also on sheet 3
VDD_5V_IO_SYS_P: R225.3 ; also on sheet 3
VDD_MUX: C106.1 C107.1 C125.1 C126.1 C163.1 C164.1 C165.1 C172.1 C173.1 Q23.2(D1) Q29.2(D1) R506.2 R522.2 U16.5(VIN) U31.5(VIN) ; also on sheet 4 7 17
VIN_PWR_BAD_L: Q502.3(D) ; also on sheet 4 7 30
BUCK_BST: C513.1 R536.2
BUCK_BST_IO: C504.1 R515.2
BUCK_FB: C97.2 R162.2 R166.1 U16.1(VFB)
BUCK_FB_IO_MID: R243.2 R250.1 R251.1
BUCK_FB_IO_MID_R: C161.1 R250.2
BUCK_FB_MID: R159.2 R161.1 R162.1
BUCK_FB_MID_R: C97.1 R161.2
BUCK_HSDR: Q23.1(G1) U16.9(DRVH)
BUCK_IO_EN: C170.1 Q501.6(D) R506.1 R507.2 U31.4(EN)
BUCK_IO_FB: C161.2 R251.2 R256.1 U31.1(VFB)
BUCK_IO_HSDR: Q29.1(G1) U31.9(DRVH)
BUCK_IO_LSDR: Q29.6(G2) R514.1 U31.7(DRVL)
BUCK_IO_SNUB: C503.1 R512.2
BUCK_IO_VREG: C171.1 U31.3(VREG5)
BUCK_IO_VSW: C504.2 L15.1 L16.1 Q29.7(S1_D2_1) R512.1 U31.8(SW)
BUCK_LSDR: Q23.6(G2) R535.1 U16.7(DRVL)
BUCK_SNUB: C508.1 R533.2
BUCK_VREG: C120.1 U16.3(VREG5)
BUCK_VSW: C513.2 L7.1 L8.1 L9.1 Q23.7(S1_D2_1) R533.1 U16.8(SW)
CARRIER_PWR_ON: R507.1 ; also on sheet 4 14 15 30
D_FORCE_OFF_G: C502.1 Q501.1(G) Q501.4(D) Q502.1(G) Q503.1(G) R502.1 R503.2
D_FORCE_OFF_L: Q501.3(G) R504.2 R505.1 ; also on sheet 1 12
VBST: R536.1 U16.10(VBST)
VBST_IO: R515.1 U31.10(VBST)

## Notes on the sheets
sheet 6
- A
- B
- C
- D
- E
- F
- G
- H
- 5V & 3V3 SYS POWER SUPPLIES
- 1
- 1
- VIN=4.5V-28V
- PCB CO-LAYOUT
- NS
- VIN=4.5V-28V
- R for test and measurement
- 2
- 2
- ROCL
- Rb1
- Vout = Vref * ((Rb1 / Rb2) + 1)
- Vref = 0.773V
- Iocl=(((Vin-Vout)*Vout)/2*L*fsw*Vin)+Vtrip/Rdson
- Rb2
- NS
- 3
- 3
- PCB CO-LAYOUT
- NS
- 4
- 4
- R for test and measurement
- Rb1
- Vout = Vref * ((Rb1 / Rb2) + 1)
- Vref = 0.773V
- Rb2
- 5
- 5
- NVIDIA CORPORATION
- 2701 SAN TOMAS EXPRESSWAY
- ASSEMBLY
- <ASSEMBLY_DESCRIPTION>
- SANTA CLARA, CA 95050, USA
- PAGE DETAIL
- 5V & 3V3 Vregs
- NV_PN
- 600-82597-BASE-900
- ALL NVIDIA DESIGN SPECIFICATIONS, REFERENCE SPECIFICATIONS, REFERENCE BOARDS, FILES, DRAWINGS, DIAGNOSTICS, LISTS AND OTHER DOCUMENTS OR INFORMATION (TOGETHER AND SEPARATELY, 'MATERIALS') ARE BEING PROVIDED 'AS IS'. THE MATERIALS MAY
- CONTAIN KNOWN AND UNKNOWN VIOLATIONS OR DEVIATIONS OF INDUSTRY STANDARDS AND SPECIFICATIONS. NVIDIA MAKES NO WARRANTIES, EXPRESSED, IMPLIED, STATUTORY OR OTHERWISE WITH RESPECT TO THE MATERIALS OR OTHERWISE, AND EXPRESSLY DISCLAIMS ALL
- PCB REV
- P2597-C02
- PAGE
- 28 OF 34
- IMPLIED WARRANTIES INCLUDING, WITHOUT LIMITATION, THE WARRANTIES OF DESIGN, OF NONINFRINGEMENT, MERCHANTABILITY OR FITNESS FOR A PARTICULAR PURPOSE, OR ARISING FROM A COURSE OF DEALING, TRADE USAGE, TRADE PRACTICE, OR INDUSTRY STANDARDS.
- BOM REV
- A
- DATE
- 23-OCT-2017
- A
- B
- C
- D
- E
- F
- G
- H
